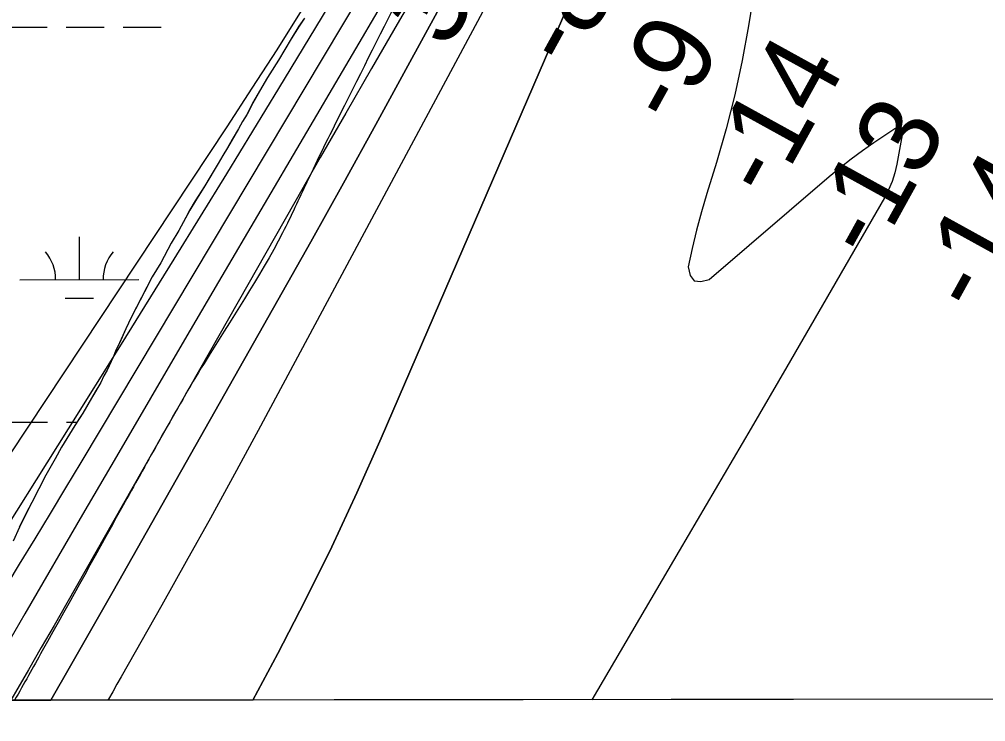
# Model space of a CAD drawing. Extents: x 3297716 to 3335574, y 688621 to 713991.
# Drawn here: x 3319561 to 3320374, y 693999 to 694591 of the extents above; entities that cross this region are included whole.
import ezdxf

# ---------------------------------------------------------------- set-up
doc = ezdxf.new("R2010")
doc.units = 0
for name, color, linetype in [('V-GRID-FRAM', 7, 'Continuous'), ('V-RIVR-EDGE', 7, 'Continuous'), ('V-RIVR-RANG', 7, 'Continuous'), ('V-SITE-VEGE', 7, 'Continuous'), ('V-TOPO-DPTH', 7, 'Continuous'), ('V-TOPO-MAJR', 7, 'Continuous'), ('V-TOPO-MINR', 7, 'Continuous'), ('V-TOPO-WATR', 7, 'Continuous'), ('V-WETL-SWMP', 7, 'Continuous')]:
    doc.layers.add(name, color=color, linetype=linetype)

msp = doc.modelspace()

# ---------------------------------------------------------------- linework, layer by layer
at = {"layer": 'V-GRID-FRAM'}
msp.add_lwpolyline([(3301838.48, 712184.22), (3333346.19, 712216.3), (3333372.64, 694031.53), (3301849.06, 693999.43), (3301838.48, 712184.22)], dxfattribs=at)
at = {"layer": 'V-RIVR-EDGE'}
msp.add_spline([(3321618.45, 701061.3), (3321639.17, 701040.92), (3321661.92, 701020.55), (3321674.32, 701007.67), (3321694.16, 700986.07), (3321717.72, 700957.41), (3321720.61, 700953.26), (3321724.75, 700950.76), (3321726.82, 700949.51), (3321730.12, 700946.19), (3321742.93, 700927.09), (3321753.65, 700905.93), (3321756.11, 700893.9), (3321759.81, 700884.36), (3321768.06, 700867.34), (3321776.73, 700853.23), (3321786.64, 700837.46), (3321794.49, 700827.9), (3321804.41, 700817.1), (3321812.69, 700810.04), (3321821.8, 700809.18), (3321830.09, 700806.68), (3321833.39, 700803.77), (3321835.87, 700798.79), (3321840.83, 700792.97), (3321849.52, 700787.56), (3321852, 700783.83), (3321866.46, 700765.14), (3321875.54, 700751.02), (3321880.08, 700741.06), (3321885.01, 700725.72), (3321889.55, 700717), (3321895.75, 700710.35), (3321901.94, 700699.15), (3321908.12, 700684.63), (3321912.22, 700664.31), (3321919.16, 700623.67), (3321922, 700598.79), (3321922.33, 700564.8), (3321921.8, 700517.55), (3321919.28, 700502.22), (3321912.99, 700476.13), (3321905.84, 700433.04), (3321899.49, 700379.59), (3321893.61, 700348.1), (3321887.31, 700316.2), (3321880.2, 700288.86), (3321874.74, 700259.03), (3321869.25, 700218.84), (3321863.73, 700164.56), (3321860.77, 700141.35), (3321859.51, 700133.9), (3321857.38, 700109.86), (3321857.72, 700080.85), (3321854.3, 700038.58), (3321847.95, 699987.61), (3321847.83, 699937.46), (3321848.6, 699913.83), (3321849.33, 699873.21), (3321853.78, 699830.51), (3321854.96, 699803.15), (3321853.26, 699786.99), (3321851.54, 699762.54), (3321847.36, 699747.63), (3321844.45, 699743.9), (3321843.17, 699728.57), (3321839.41, 699718.22), (3321831.1, 699708.71), (3321827.36, 699705.81), (3321826.94, 699701.67), (3321826.9, 699687.16), (3321823.15, 699678.88), (3321813.6, 699670.62), (3321798.66, 699664.44), (3321785.76, 699644.16), (3321779.93, 699632.57), (3321773.21, 699598.6), (3321768.1, 699540.58), (3321765.15, 699519.86), (3321762.59, 699492.93), (3321757.53, 699458.54), (3321751.27, 699439.49), (3321741.26, 699415.47), (3321732.08, 699391.04), (3321722.08, 699368.27), (3321716.24, 699354.61), (3321712.46, 699334.72), (3321711.17, 699313.17), (3321708.16, 699269.24), (3321710.2, 699258.88), (3321713.08, 699250.99), (3321718.86, 699240.62), (3321727.54, 699231.89), (3321733.75, 699226.9), (3321735.8, 699219.85), (3321729.5, 699186.29), (3321720.32, 699159.37), (3321709.07, 699134.53), (3321700.31, 699115.49), (3321685.36, 699100.6), (3321679.12, 699094.4), (3321674.96, 699087.37), (3321674.54, 699083.64), (3321670.34, 699063.75), (3321660.32, 699031.86), (3321651.17, 699018.62), (3321638.28, 699002.49), (3321632.02, 698987.58), (3321625.76, 698968.12), (3321619.46, 698936.22), (3321615.66, 698908.04), (3321607.29, 698875.32), (3321593.49, 698825.61), (3321583.49, 698805.33), (3321580.14, 698792.07), (3321580.11, 698777.57), (3321580.08, 698768.03), (3321572.16, 698748.16), (3321567.94, 698717.91), (3321559.1, 698663.64), (3321555.74, 698647.06), (3321554.07, 698638.36), (3321550.73, 698631.74), (3321551.53, 698617.65), (3321548.59, 698601.9), (3321548.13, 698586.15), (3321543.97, 698577.46), (3321538.14, 698566.28), (3321534.37, 698551.37), (3321535.17, 698541.42), (3321533.49, 698532.72), (3321521.4, 698502.08), (3321503.45, 698451.14), (3321490.53, 698421.75), (3321481.38, 698409.33), (3321476.81, 698403.96), (3321474.3, 698395.26), (3321466.79, 698374.55), (3321458.45, 698355.09), (3321454.28, 698343.91), (3321453.02, 698339.36), (3321455.92, 698336.45), (3321456.74, 698333.13), (3321454.65, 698329.4), (3321448.83, 698321.96), (3321440.11, 698313.69), (3321430.98, 698308.32), (3321420.6, 698301.3), (3321418.1, 698296.34), (3321412.68, 698284.33), (3321407.28, 698277.71), (3321395.61, 698252.46), (3321375.16, 698198.21), (3321359.31, 698158.46), (3321345.97, 698126.16), (3321337.19, 698093.85), (3321334.25, 698078.94), (3321334.23, 698070.24), (3321336.69, 698059.45), (3321328.74, 698032.12), (3321314.56, 697996.09), (3321306.62, 697968.76), (3321301.21, 697958.41), (3321293.31, 697951.38), (3321284.15, 697933.99), (3321274.57, 697915.37), (3321271.23, 697904.6), (3321272.45, 697893.82), (3321272.42, 697881.8), (3321266.57, 697862.33), (3321256.95, 697828.37), (3321254.44, 697817.6), (3321249.85, 697808.08), (3321241.51, 697787.79), (3321233.61, 697774.54), (3321226.53, 697762.13), (3321220.27, 697745.56), (3321216.1, 697733.97), (3321215.67, 697727.34), (3321217.73, 697725.67), (3321219.8, 697723.6), (3321219.37, 697718.62), (3321208.12, 697691.71), (3321197.7, 697668.11), (3321194.79, 697666.04), (3321191.06, 697666.05), (3321191.45, 697656.52), (3321188.95, 697651.55), (3321185.63, 697649.07), (3321180.24, 697647.84), (3321181.04, 697635.82), (3321179.37, 697630.85), (3321174.8, 697625.89), (3321172.29, 697619.26), (3321170.2, 697612.22), (3321164.33, 697585.71), (3321162.65, 697577.01), (3321158.92, 697575.78), (3321154.35, 697570.81), (3321148.51, 697557.56), (3321144.77, 697550.53), (3321143.91, 697539.34), (3321140.58, 697535.62), (3321134.77, 697529.41), (3321132.68, 697525.27), (3321128.5, 697509.53), (3321122.64, 697486.75), (3321103.06, 697447.42), (3321100.98, 697441.63), (3321100.95, 697432.92), (3321091.79, 697415.12), (3321084.3, 697404.36), (3321071.4, 697382.01), (3321064.34, 697376.64), (3321056.87, 697372.93), (3321048.14, 697363.42), (3321041.07, 697351), (3321031.9, 697332.37), (3321023.56, 697312.08), (3321015.63, 697288.06), (3321006.43, 697254.51), (3320994.76, 697229.67), (3320983.51, 697207.32), (3320979.36, 697203.6), (3320975.6, 697193.66), (3320968.09, 697172.54), (3320962.64, 697145.61), (3320955.95, 697122.42), (3320943.84, 697086.8), (3320940.48, 697069.4), (3320936.31, 697061.12), (3320926.34, 697048.71), (3320920.93, 697043.34), (3320909.64, 697002.33), (3320899.61, 696969.2), (3320887.51, 696935.24), (3320880.84, 696920.33), (3320879.58, 696912.46), (3320883.28, 696900.43), (3320882.85, 696894.63), (3320876.18, 696878.07), (3320871.56, 696854.04), (3320866.95, 696835.81), (3320859.86, 696815.94), (3320857.35, 696806.82), (3320853.17, 696794.4), (3320849.83, 696784.46), (3320847.3, 696766.64), (3320843.13, 696755.46), (3320836.06, 696746.78), (3320830.23, 696736.43), (3320825.62, 696714.06), (3320819.78, 696699.98), (3320814.39, 696700.82), (3320813.53, 696688.39), (3320798.51, 696648.22), (3320788.51, 696625.45), (3320782.7, 696621.73), (3320776.44, 696606.83), (3320773.11, 696599.38), (3320766.05, 696592.76), (3320752.32, 696573.31), (3320739.41, 696550.14), (3320720.25, 696512.05), (3320700.68, 696473.55), (3320668.58, 696401.51), (3320646.49, 696351.83), (3320619.82, 696291.38), (3320606.9, 696264.05), (3320587.72, 696216.85), (3320576.88, 696191.59), (3320559.79, 696152.26), (3320552.68, 696128.24), (3320546.41, 696106.29), (3320536.39, 696076.47), (3320526.77, 696040.43), (3320506.73, 695984.11), (3320462.47, 695850.34), (3320450.34, 695806.02), (3320441.99, 695784.08), (3320420.24, 695702.06), (3320413.95, 695672.23), (3320409.31, 695639.92), (3320408.02, 695624.17), (3320406.74, 695608.42), (3320408.37, 695594.32), (3320410.83, 695583.96), (3320416.18, 695571.92), (3320421.98, 695567.35), (3320430.26, 695563.18), (3320436.88, 695558.19), (3320439.76, 695552.38), (3320445.95, 695539.93), (3320448.82, 695529.15), (3320449.62, 695514.64), (3320448.35, 695507.18), (3320445.85, 695499.32), (3320439.61, 695490.63), (3320432.95, 695478.62), (3320425.04, 695464.14), (3320423.36, 695454.61), (3320416.68, 695438.87), (3320407.94, 695423.56), (3320400.05, 695416.95), (3320392.16, 695411.99), (3320377.64, 695405.4), (3320369.77, 695408.32), (3320357.76, 695410.42), (3320346.57, 695411.28), (3320320.43, 695400.15), (3320298.01, 695386.53), (3320249, 695343.13), (3320201.63, 695295.58), (3320188.34, 695286.49), (3320177.97, 695282.37), (3320168.43, 695279.5), (3320163.44, 695274.95), (3320158.02, 695258.8), (3320150.48, 695228.14), (3320140.07, 695207.45), (3320125.48, 695174.32), (3320115.05, 695149.48), (3320110.04, 695134.99), (3320108.37, 695129.6), (3320108.36, 695125.87), (3320112.48, 695115.91), (3320113.71, 695108.45), (3320113.28, 695102.65), (3320106.62, 695091.47), (3320104.12, 695086.92), (3320100.38, 695081.54), (3320098.3, 695077.82), (3320098.29, 695074.91), (3320104.89, 695063.71), (3320105.7, 695055.41), (3320108.15, 695041.32), (3320112.69, 695030.11), (3320122.19, 695016.41), (3320128.39, 695010.18), (3320133.76, 695004.36), (3320135.82, 694999.39), (3320135.81, 694993.17), (3320132.46, 694981.16), (3320110.39, 694941.42), (3320095, 694917.83), (3320080.04, 694902.95), (3320068.41, 694893.44), (3320055.95, 694881.45), (3320033.07, 694848.77), (3319991.89, 694787.94), (3319966.93, 694752.36), (3319939.88, 694710.15), (3319919.91, 694678.69), (3319900.35, 694647.24), (3319884.95, 694618.27), (3319831.21, 694511.88), (3319802.89, 694453.92), (3319782.47, 694411.28), (3319716.3, 694301.19), (3319680.91, 694240.35), (3319651.35, 694187.37), (3319580.16, 694059.05), (3319556.78, 694017.46)], degree=3, dxfattribs=at)
at = {"layer": 'V-SITE-VEGE'}
for p, q in [((3319800.91, 694592.08), (3319796.26, 694585.1)), ((3319796.26, 694585.1), (3319789.64, 694574.64)), ((3319789.64, 694574.64), (3319779.06, 694556.53)), ((3319779.06, 694556.53), (3319769.79, 694541.88)), ((3319769.79, 694541.88), (3319757.24, 694520.28)), ((3319757.24, 694520.28), (3319752.64, 694511.24)), ((3319752.64, 694511.24), (3319748.66, 694504.97)), ((3319748.66, 694504.97), (3319745.38, 694498.7)), ((3319745.38, 694498.7), (3319736.13, 694482.68)), ((3319732.15, 694476.41), (3319728.2, 694469.44)), ((3319736.13, 694482.68), (3319732.15, 694476.41)), ((3319728.2, 694469.44), (3319716.95, 694450.62)), ((3319716.95, 694450.62), (3319709, 694438.07)), ((3319709, 694438.07), (3319704.37, 694430.4)), ((3319704.37, 694430.4), (3319695.16, 694413.01)), ((3319695.16, 694413.01), (3319688.53, 694402.55)), ((3319688.53, 694402.55), (3319679.99, 694385.85)), ((3319679.99, 694385.85), (3319672.71, 694374)), ((3319672.71, 694374), (3319654.96, 694339.92)), ((3319654.96, 694339.92), (3319650.38, 694330.19)), ((3319650.38, 694330.19), (3319645.15, 694318.38)), ((3319645.15, 694318.38), (3319641.88, 694311.44)), ((3319639.93, 694306.58), (3319634.7, 694295.46)), ((3319641.88, 694311.44), (3319639.93, 694306.58)), ((3319632.06, 694290.59), (3319629.44, 694285.04)), ((3319634.7, 694295.46), (3319632.06, 694290.59)), ((3319629.44, 694285.04), (3319621.51, 694271.79)), ((3319621.51, 694271.79), (3319614.24, 694259.25)), ((3319614.24, 694259.25), (3319607.62, 694248.79)), ((3319607.62, 694248.79), (3319596.36, 694230.66)), ((3319596.36, 694230.66), (3319591.09, 694220.92)), ((3319591.09, 694220.92), (3319583.17, 694206.99)), ((3319583.17, 694206.99), (3319571.34, 694184.04)), ((3319571.34, 694184.04), (3319568.71, 694179.16)), ((3319568.71, 694179.16), (3319560.84, 694163.18)), ((3319560.84, 694163.18), (3319555.61, 694151.37))]:
    msp.add_line(p, q, dxfattribs=at)
at = {"layer": 'V-TOPO-DPTH'}
for points in [[(3320262.9, 695375.65), (3320100.76, 695036.46), (3320070.34, 694974.45), (3320039.09, 694912.88), (3320006.59, 694851.95), (3319973.26, 694791.46), (3319938.6, 694730.05), (3319921.9, 694700.63), (3319905.1, 694671.26), (3319888.14, 694641.99), (3319871.09, 694612.77), (3319728.58, 694370.02), (3319699.86, 694321.01), (3319671.2, 694271.99), (3319642.6, 694222.92), (3319614.05, 694173.82), (3319565.53, 694090.23), (3319561.28, 694082.9), (3319557.02, 694075.58), (3319552.75, 694068.26), (3319548.49, 694060.95), (3319523.08, 694017.43), (3319587.32, 694017.49)], [(3319587.32, 694017.49), (3319604.01, 694046.58), (3319621.92, 694078), (3319639.78, 694109.45), (3319778.44, 694354.54), (3319806.09, 694403.69), (3319833.59, 694452.94), (3319860.84, 694502.32), (3319887.93, 694551.78), (3319937.36, 694642.55), (3319939.61, 694646.7), (3319941.84, 694650.87), (3319944.05, 694655.04), (3319946.25, 694659.22), (3319999.47, 694761.18), (3320027.99, 694816.49), (3320056.12, 694872), (3320083.68, 694927.78), (3320110.86, 694983.76), (3320278.54, 695333.63)], [(3319587.32, 694017.49), (3319604.01, 694046.58), (3319621.92, 694078), (3319639.78, 694109.45), (3319778.44, 694354.54), (3319806.09, 694403.69), (3319833.59, 694452.94), (3319860.84, 694502.32), (3319887.93, 694551.78), (3319937.36, 694642.55), (3319939.61, 694646.7), (3319941.84, 694650.87), (3319944.05, 694655.04), (3319946.25, 694659.22), (3319999.47, 694761.18), (3320027.99, 694816.49), (3320056.12, 694872), (3320083.68, 694927.78), (3320110.86, 694983.76), (3320278.54, 695333.63)], [(3320322.02, 695286.33), (3320041.64, 694646.14), (3320038.66, 694639.34), (3320035.69, 694632.55), (3320032.73, 694625.76), (3320029.76, 694618.96), (3320026.8, 694612.16), (3320023.85, 694605.36), (3320020.91, 694598.56), (3320017.97, 694591.75), (3319865.51, 694238.17), (3319845.02, 694192.21), (3319823.79, 694146.61), (3319801.44, 694101.55), (3319778.35, 694056.85), (3319757.5, 694017.67), (3319587.32, 694017.49)], [(3319757.5, 694017.67), (3319778.35, 694056.85), (3319801.44, 694101.55), (3319823.79, 694146.61), (3319845.02, 694192.21), (3319865.51, 694238.17), (3320017.97, 694591.75), (3320020.91, 694598.56), (3320023.85, 694605.36), (3320026.8, 694612.16), (3320029.76, 694618.96), (3320032.73, 694625.76), (3320035.69, 694632.55), (3320038.66, 694639.34), (3320041.64, 694646.14), (3320322.02, 695286.33)], [(3320903.37, 695135.72), (3320777.69, 694328.58), (3320777.68, 694322.33), (3320776.95, 694316.12), (3320775.72, 694309.94), (3320755.89, 694233.86), (3320751.6, 694218.81), (3320746.86, 694203.92), (3320741.44, 694189.26), (3320735.57, 694174.75), (3320676.57, 694037.97), (3320668, 694018.59), (3319757.5, 694017.67)]]:
    msp.add_lwpolyline(points, dxfattribs=at)
at = {"layer": 'V-TOPO-MAJR'}
msp.add_lwpolyline([(3320189.11, 695279.22), (3319865.6, 694709.41), (3319862.07, 694703.25), (3319858.5, 694697.12), (3319854.87, 694691.02), (3319851.2, 694684.94), (3319818.34, 694631.04), (3319798.03, 694598.14), (3319777.48, 694565.4), (3319756.56, 694532.89), (3319735.39, 694500.54), (3319521.97, 694178.31), (3319502.95, 694149.49), (3319484, 694120.62), (3319465.14, 694091.69), (3319446.36, 694062.71), (3319417.05, 694017.32)], dxfattribs=at)
at = {"layer": 'V-TOPO-MINR'}
for points in [[(3320259.43, 695384.9), (3320184.28, 695228.11), (3320141.68, 695141.53), (3320097.89, 695055.56), (3320052.34, 694970.52), (3320005.61, 694886.09), (3319912.97, 694722.73), (3319900.85, 694701.54), (3319888.64, 694680.4), (3319876.28, 694659.34), (3319863.83, 694638.34), (3319612.59, 694217.84), (3319599.71, 694196.36), (3319586.79, 694174.91), (3319573.8, 694153.5), (3319560.77, 694132.11), (3319539.53, 694097.37), (3319537.09, 694093.37), (3319534.66, 694089.37), (3319532.24, 694085.37), (3319529.82, 694081.37), (3319491.29, 694017.4)], [(3320262.9, 695375.65), (3320100.76, 695036.46), (3320070.34, 694974.45), (3320039.09, 694912.88), (3320006.59, 694851.95), (3319973.26, 694791.46), (3319938.6, 694730.05), (3319921.9, 694700.63), (3319905.1, 694671.26), (3319888.14, 694641.99), (3319871.09, 694612.77), (3319728.58, 694370.02), (3319699.86, 694321.01), (3319671.2, 694271.99), (3319642.6, 694222.92), (3319614.05, 694173.82), (3319565.53, 694090.23), (3319561.28, 694082.9), (3319557.02, 694075.58), (3319552.75, 694068.26), (3319548.49, 694060.95), (3319523.08, 694017.43)], [(3320266.94, 695364.76), (3320003.63, 694814.92), (3319990.89, 694788.96), (3319977.82, 694763.18), (3319964.25, 694737.65), (3319950.36, 694712.29), (3319936.17, 694687.09), (3319921.91, 694661.93), (3319907.55, 694636.83), (3319893.12, 694611.76), (3319878.79, 694586.99), (3319857.19, 694549.55), (3319835.64, 694512.07), (3319814.17, 694474.55), (3319792.76, 694436.99), (3319600.79, 694099.36), (3319590.07, 694080.58), (3319579.31, 694061.83), (3319568.48, 694043.11), (3319557.61, 694024.42), (3319553.54, 694017.46)], [(3320322.02, 695286.33), (3320041.64, 694646.14), (3320038.66, 694639.34), (3320035.69, 694632.55), (3320032.73, 694625.76), (3320029.76, 694618.96), (3320026.8, 694612.16), (3320023.85, 694605.36), (3320020.91, 694598.56), (3320017.97, 694591.75), (3319865.51, 694238.17), (3319845.02, 694192.21), (3319823.79, 694146.61), (3319801.44, 694101.55), (3319778.35, 694056.85), (3319757.5, 694017.67)], [(3320183.25, 695244.21), (3320156.18, 695191.17), (3320128.03, 695138.7), (3320099.15, 695086.6), (3319888.68, 694715.89), (3319880.96, 694702.42), (3319873.16, 694688.99), (3319865.25, 694675.62), (3319857.26, 694662.3), (3319778.92, 694532.83), (3319735.09, 694460.84), (3319691.01, 694389.01), (3319646.54, 694317.42), (3319601.81, 694245.99), (3319531.16, 694133.83), (3319521.61, 694118.57), (3319512.11, 694103.28), (3319502.7, 694087.94), (3319493.35, 694072.56), (3319459.99, 694017.36)], [(3320271.53, 695243.68), (3320258.9, 695217.82), (3319989.84, 694672.99), (3319980.3, 694653.9), (3319970.63, 694634.88), (3319960.76, 694615.96), (3319950.78, 694597.1), (3319761.86, 694244.69), (3319741.9, 694207.78), (3319721.78, 694170.96), (3319701.39, 694134.28), (3319680.84, 694097.7), (3319646.52, 694037.12), (3319642.98, 694030.9), (3319639.43, 694024.69), (3319635.85, 694018.5), (3319635.3, 694017.54)], [(3320238.15, 694976.62), (3320174.68, 694585.41), (3320169.35, 694556.3), (3320163.2, 694527.39), (3320155.82, 694498.75), (3320147.63, 694470.32), (3320139.49, 694444.18), (3320134.99, 694428.9), (3320130.8, 694413.52), (3320127.1, 694398.03), (3320123.71, 694382.46), (3320125.56, 694375.36), (3320128.92, 694370.82), (3320134.52, 694370.11), (3320141.62, 694371.95), (3320242.63, 694458.55), (3320251.75, 694466.1), (3320261.03, 694473.43), (3320270.57, 694480.43), (3320280.27, 694487.22), (3320297.76, 694499.01), (3320298.88, 694499.58), (3320301.23, 694500.07), (3320302.48, 694499.98), (3320303.44, 694499.52), (3320304.16, 694498.89), (3320304.49, 694497.99), (3320304.58, 694496.93), (3320299.56, 694469.02), (3320297.81, 694461.59), (3320295.58, 694454.33), (3320292.6, 694447.36), (3320289.13, 694440.56), (3320236.88, 694350.19), (3320206.85, 694298.38), (3320176.76, 694246.6), (3320146.56, 694194.89), (3320116.3, 694143.21), (3320042.77, 694017.96)]]:
    msp.add_lwpolyline(points, dxfattribs=at)
at = {"layer": 'V-TOPO-WATR'}
msp.add_lwpolyline([(3320278.54, 695333.63), (3320110.86, 694983.76), (3320083.68, 694927.78), (3320056.12, 694872), (3320027.99, 694816.49), (3319999.47, 694761.18), (3319946.25, 694659.22), (3319944.05, 694655.04), (3319941.84, 694650.87), (3319939.61, 694646.7), (3319937.36, 694642.55), (3319887.93, 694551.78), (3319860.84, 694502.32), (3319833.59, 694452.94), (3319806.09, 694403.69), (3319778.44, 694354.54), (3319639.78, 694109.45), (3319621.92, 694078), (3319604.01, 694046.58), (3319587.32, 694017.49)], dxfattribs=at)
at = {"layer": 'V-WETL-SWMP'}
for p, q in [((3319800.88, 694592.1), (3319796.23, 694585.12)), ((3319552.34, 694584.26), (3319584.34, 694584.29)), ((3319600.34, 694584.3), (3319632.34, 694584.33)), ((3319648.34, 694584.34), (3319680.34, 694584.37)), ((3319796.23, 694585.12), (3319789.6, 694574.65)), ((3319789.6, 694574.65), (3319779.03, 694556.54)), ((3319779.03, 694556.54), (3319773.73, 694548.17)), ((3319769.76, 694541.89), (3319757.21, 694520.3)), ((3319773.73, 694548.17), (3319769.76, 694541.89)), ((3319757.21, 694520.3), (3319752.61, 694511.26)), ((3319752.61, 694511.26), (3319748.63, 694504.98)), ((3319748.63, 694504.98), (3319745.34, 694498.72)), ((3319745.34, 694498.72), (3319740.06, 694489.66)), ((3319740.06, 694489.66), (3319736.1, 694482.7)), ((3319732.12, 694476.42), (3319728.16, 694469.45)), ((3319736.1, 694482.7), (3319732.12, 694476.42)), ((3319728.16, 694469.45), (3319721.55, 694458.31)), ((3319721.55, 694458.31), (3319716.92, 694450.64)), ((3319716.92, 694450.64), (3319708.97, 694438.08)), ((3319708.97, 694438.08), (3319704.34, 694430.42)), ((3319704.34, 694430.42), (3319701.05, 694424.15)), ((3319701.05, 694424.15), (3319695.13, 694413.02)), ((3319695.13, 694413.02), (3319688.5, 694402.56)), ((3319611.36, 694371.7), (3319611.33, 694407.7)), ((3319688.5, 694402.56), (3319679.96, 694385.87)), ((3319679.96, 694385.87), (3319672.68, 694374.02)), ((3319561.36, 694371.66), (3319661.36, 694371.75)), ((3319672.68, 694374.02), (3319666.1, 694361.49)), ((3319599.37, 694356.26), (3319623.37, 694356.28)), ((3319666.1, 694361.49), (3319654.93, 694339.93)), ((3319654.93, 694339.93), (3319650.34, 694330.2)), ((3319650.34, 694330.2), (3319645.12, 694318.4)), ((3319645.12, 694318.4), (3319641.85, 694311.45)), ((3319639.9, 694306.59), (3319634.67, 694295.48)), ((3319641.85, 694311.45), (3319639.9, 694306.59)), ((3319632.03, 694290.6), (3319629.41, 694285.05)), ((3319634.67, 694295.48), (3319632.03, 694290.6)), ((3319629.41, 694285.05), (3319624.78, 694277.38)), ((3319624.78, 694277.38), (3319621.48, 694271.8)), ((3319621.48, 694271.8), (3319614.21, 694259.27)), ((3319614.21, 694259.27), (3319611.56, 694255.08)), ((3319552.62, 694251.58), (3319584.62, 694251.61)), ((3319607.59, 694248.8), (3319596.33, 694230.67)), ((3319600.62, 694251.63), (3319609.38, 694251.63)), ((3319611.56, 694255.08), (3319607.59, 694248.8)), ((3319596.33, 694230.67), (3319591.06, 694220.93)), ((3319591.06, 694220.93), (3319583.14, 694207)), ((3319583.14, 694207), (3319571.31, 694184.05)), ((3319571.31, 694184.05), (3319568.68, 694179.18)), ((3319568.68, 694179.18), (3319560.81, 694163.19))]:
    msp.add_line(p, q, dxfattribs=at)
for centre, start, end in [((3319556.12, 694372.13), 359.27624, 40.81989), ((3319666.6, 694372.23), 139.27624, 180.8199)]:
    msp.add_arc(centre, 35.25, start, end, dxfattribs=at)

# ---------------------------------------------------------------- texts
at = {"layer": 'V-RIVR-RANG'}
for s, p in [('3.5', (3319921.67, 694564.41)), ('-8', (3320026.31, 694547.07)), ('-9', (3320114.13, 694499.24)), ('-14', (3320194.18, 694437.33)), ('-13', (3320279.97, 694385.8)), ('-14', (3320369.06, 694340.29))]:
    msp.add_text(s, height=67, rotation=61.11531, dxfattribs=at).set_placement(p)

doc.saveas('drawing.dxf')
